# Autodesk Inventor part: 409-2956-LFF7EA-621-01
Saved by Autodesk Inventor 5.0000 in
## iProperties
Created: 2010-06
Part Number: 409-2956-LFF7EA-621-01
Cost Center: 0 lbmass
Material: A36 STEEL PLATE
Document SubType Name: Sheet Metal
Designer: S. Boerckel
Authority: 0 in^3
Mass: 8052.98 g
Surface Area: 761.54 cm^2
Volume: 1024.55 cm^3
Density: 7.86 g/cm^3
Flat Pattern Width: 15.24 cm
Flat Pattern Length: 15.24 cm
Flat Pattern Area: 232.258 cm^2
Sheet Metal Rule: 1-3/4" THK
Sheet Metal Width: 10.0000 in
Sheet Metal Length: 50.0000 in^2
Description: STRAINER FOOT PLATE
User Status: BURN- DRILL-TAP
SaveDate: 2008-01-15
SaveTime: 10:24
FileName: Sheet Metal
Wide: =<Flat Pattern Width>cm
Length: =<Flat Pattern Length>cm
Thickness: 1.7500 in
SMR: =<Sheet Metal Rule> - <Material>
Author: S. Boerckel
Revision Number: 0
Subject: DEMIN WATER FORWARDING PUMP SKID-7EA
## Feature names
1. Hole2
2. Plate1
